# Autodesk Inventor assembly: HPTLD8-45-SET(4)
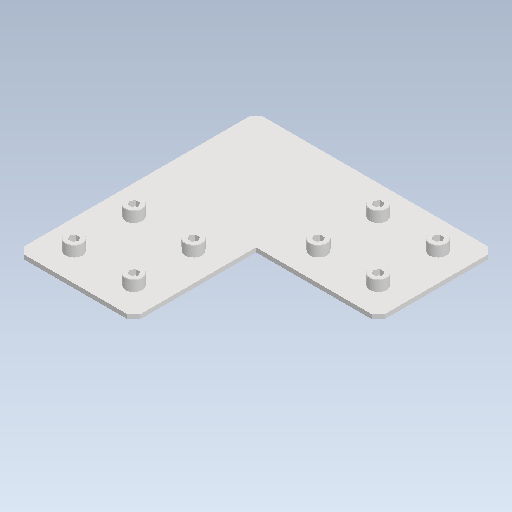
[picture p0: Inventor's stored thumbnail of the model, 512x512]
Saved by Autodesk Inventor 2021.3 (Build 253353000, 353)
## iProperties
Created: 2022-02
Part Number: HPTLD8-45-SET(4)
Document SubType Name: Assembly
Designer: kengo
Author: kengo
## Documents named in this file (4)
- C:\Users\kengo\Documents\S2S_frame\SDC345\frame_misumi_ver12\HPTLD8-45-SET(4).iam
- C:\Users\kengo\Documents\S2S_frame\SDC345\frame_misumi_ver12\HPTLD8-45.ipt
- C:\Users\kengo\Documents\S2S_frame\SDC345\frame_misumi_ver12\HNTT8-8.ipt
- C:\Users\kengo\Documents\S2S_frame\SDC345\frame_misumi_ver12\CBM8-15.ipt
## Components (17 placed, 3 different names)
1. HPTLD8-45
2. HNTT8-8
3. CBM8-15
4. HNTT8-8:1
5. CBM8-15:1
6. HNTT8-8:2
7. CBM8-15:2
8. HNTT8-8:3
9. CBM8-15:3
10. HNTT8-8:4
11. CBM8-15:4
12. HNTT8-8:5
13. CBM8-15:5
14. HNTT8-8:6
15. CBM8-15:6
16. HNTT8-8:7
17. CBM8-15:7
